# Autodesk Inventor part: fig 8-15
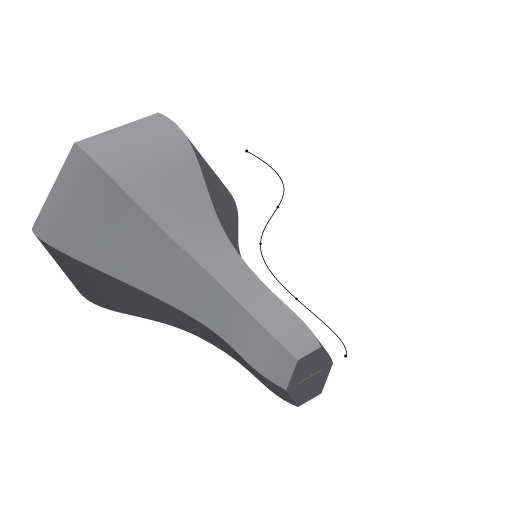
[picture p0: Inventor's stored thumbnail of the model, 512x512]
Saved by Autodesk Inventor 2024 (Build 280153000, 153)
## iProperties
Created: 2004-05
Part Number: fig 8-15
Document SubType Name: Modeling
Designer: CADCIM Technologies
Manufacturer: Standard
Standards Organization: Custom
Density: 1 g/cm^3
Material: Generic
Appearance: Default
Author: CADCIM Technologies
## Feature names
1. Sweep7
## Parameters: d6 = 0, d7 = 0
